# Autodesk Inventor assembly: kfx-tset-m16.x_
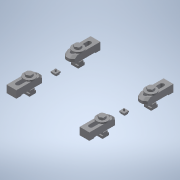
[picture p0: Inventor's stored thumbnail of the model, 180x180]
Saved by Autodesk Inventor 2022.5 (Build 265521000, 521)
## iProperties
Created: 2021-10
Part Number: kfx-tset-m16.x_
Material: 一般
Document SubType Name: Assembly
Designer: ImaoCorp
Sending System: SOLIDWORKS 2019-2019304
MC: AMD64
MC_MODEL: Intel64 Family 6 Model 60 Stepping 3, GenuineIntel
OS: Windows_NT
FRU: Parasolid Version 31.0, build 290,  9- 1-2019
FORMAT: text
GUISE: transmit
KEY: kfx-tset-m16
FILE: kfx-tset-m16.x_t
DATE: Thu Oct 14 10:02:43 2021
Author: ImaoCorp
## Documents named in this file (15)
- X:\14_SW2022-Inv2022\00_全2023-1023新製品(TCC)まで\k\kfx-tset-m16\KFX-TSET-M16.iam
- X:\14_SW2022-Inv2022\00_全2023-1023新製品(TCC)まで\k\kfx-tset-m16\kfx-tset-m16_01.ipt
- X:\14_SW2022-Inv2022\00_全2023-1023新製品(TCC)まで\k\kfx-tset-m16\kfx-tset-m16_02.ipt
- X:\14_SW2022-Inv2022\00_全2023-1023新製品(TCC)まで\k\kfx-tset-m16\kfx-tset-m16_03.ipt
- X:\14_SW2022-Inv2022\00_全2023-1023新製品(TCC)まで\k\kfx-tset-m16\kfx-tset-m16_04.ipt
- X:\14_SW2022-Inv2022\00_全2023-1023新製品(TCC)まで\k\kfx-tset-m16\kfx-tset-m16_05.ipt
- X:\14_SW2022-Inv2022\00_全2023-1023新製品(TCC)まで\k\kfx-tset-m16\kfx-tset-m16_06.ipt
- X:\14_SW2022-Inv2022\00_全2023-1023新製品(TCC)まで\k\kfx-tset-m16\kfx-tset-m16_07.ipt
- X:\14_SW2022-Inv2022\00_全2023-1023新製品(TCC)まで\k\kfx-tset-m16\kfx-tset-m16_08.ipt
- X:\14_SW2022-Inv2022\00_全2023-1023新製品(TCC)まで\k\kfx-tset-m16\kfx-tset-m16_09.ipt
- X:\14_SW2022-Inv2022\00_全2023-1023新製品(TCC)まで\k\kfx-tset-m16\kfx-tset-m16_10.ipt
- X:\14_SW2022-Inv2022\00_全2023-1023新製品(TCC)まで\k\kfx-tset-m16\kfx-tset-m16_11.ipt
- X:\14_SW2022-Inv2022\00_全2023-1023新製品(TCC)まで\k\kfx-tset-m16\kfx-tset-m16_12.ipt
- X:\14_SW2022-Inv2022\00_全2023-1023新製品(TCC)まで\k\kfx-tset-m16\kfx-tset-m16_13.ipt
- X:\14_SW2022-Inv2022\00_全2023-1023新製品(TCC)まで\k\kfx-tset-m16\kfx-tset-m16_14.ipt
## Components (14 placed, 14 different names)
1. kfx-tset-m16_01
2. kfx-tset-m16_02
3. kfx-tset-m16_03
4. kfx-tset-m16_04
5. kfx-tset-m16_05
6. kfx-tset-m16_06
7. kfx-tset-m16_07
8. kfx-tset-m16_08
9. kfx-tset-m16_09
10. kfx-tset-m16_10
11. kfx-tset-m16_11
12. kfx-tset-m16_12
13. kfx-tset-m16_13
14. kfx-tset-m16_14
